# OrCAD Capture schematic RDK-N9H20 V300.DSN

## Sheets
1 PAGE01 - CPU: size B; rev: 1.0; company: for reference; note: N9H20; note: NHS-55FA93 V1.0
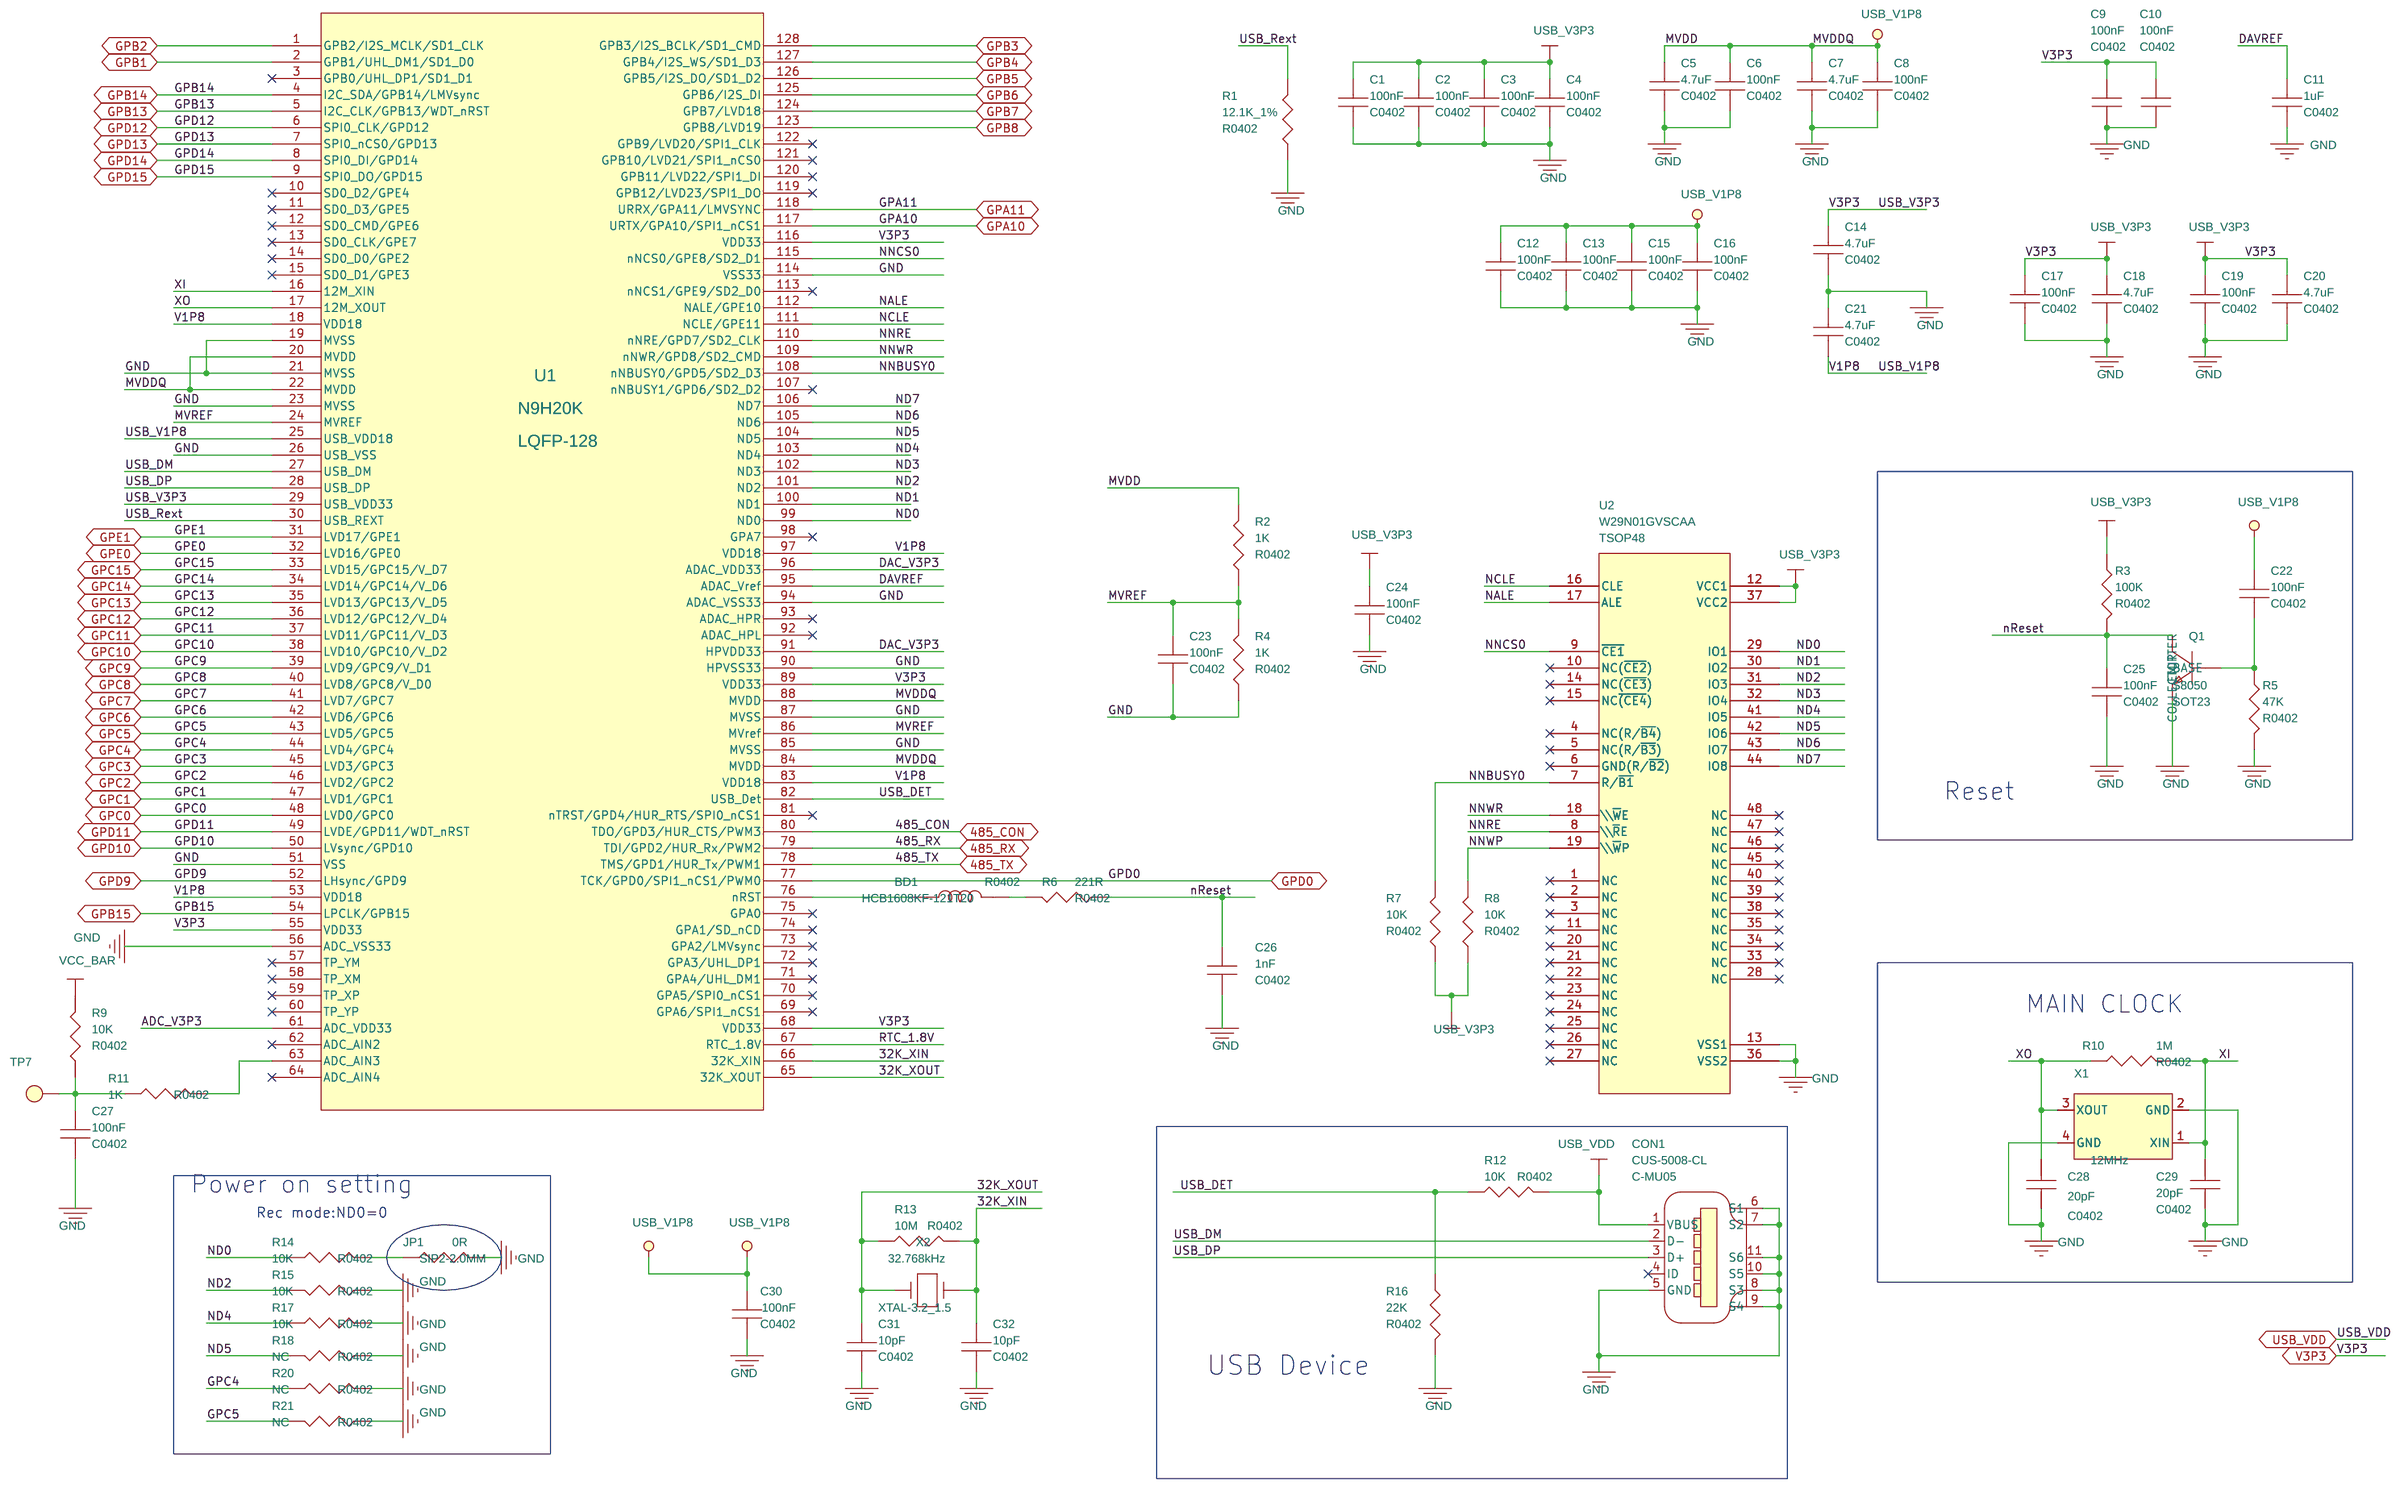
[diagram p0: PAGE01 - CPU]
2 PAGE02 - LCD: size B; note: LCD
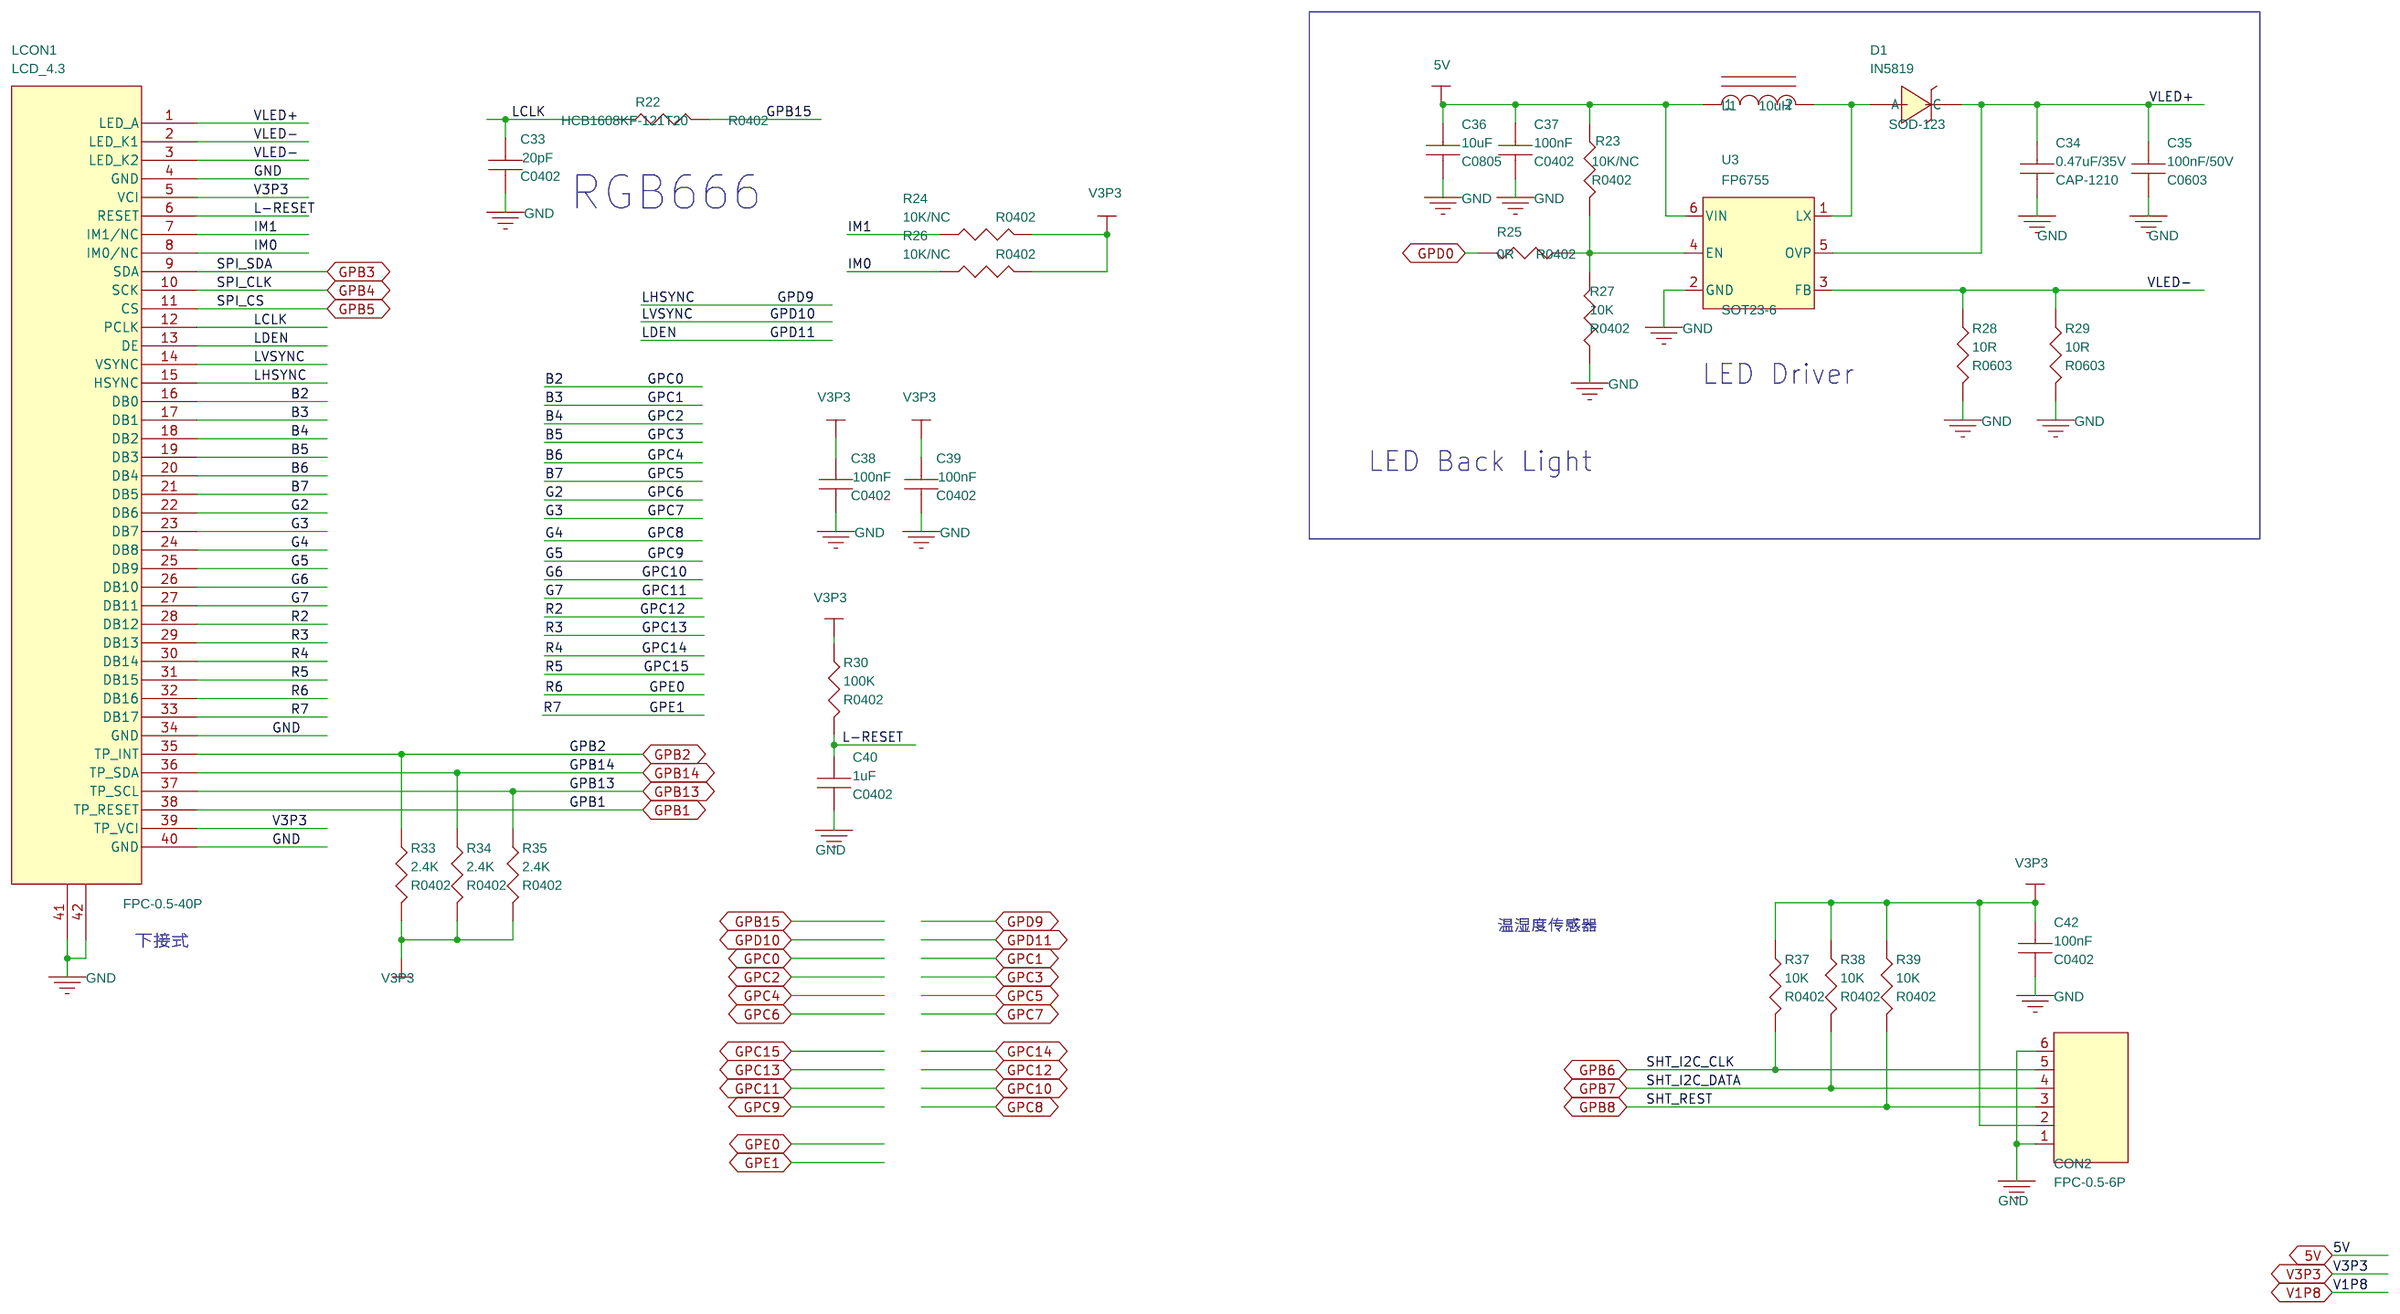
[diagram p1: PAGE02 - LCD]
3 PAGE03 - POWER,Debug: size B; note: POWER,Debug
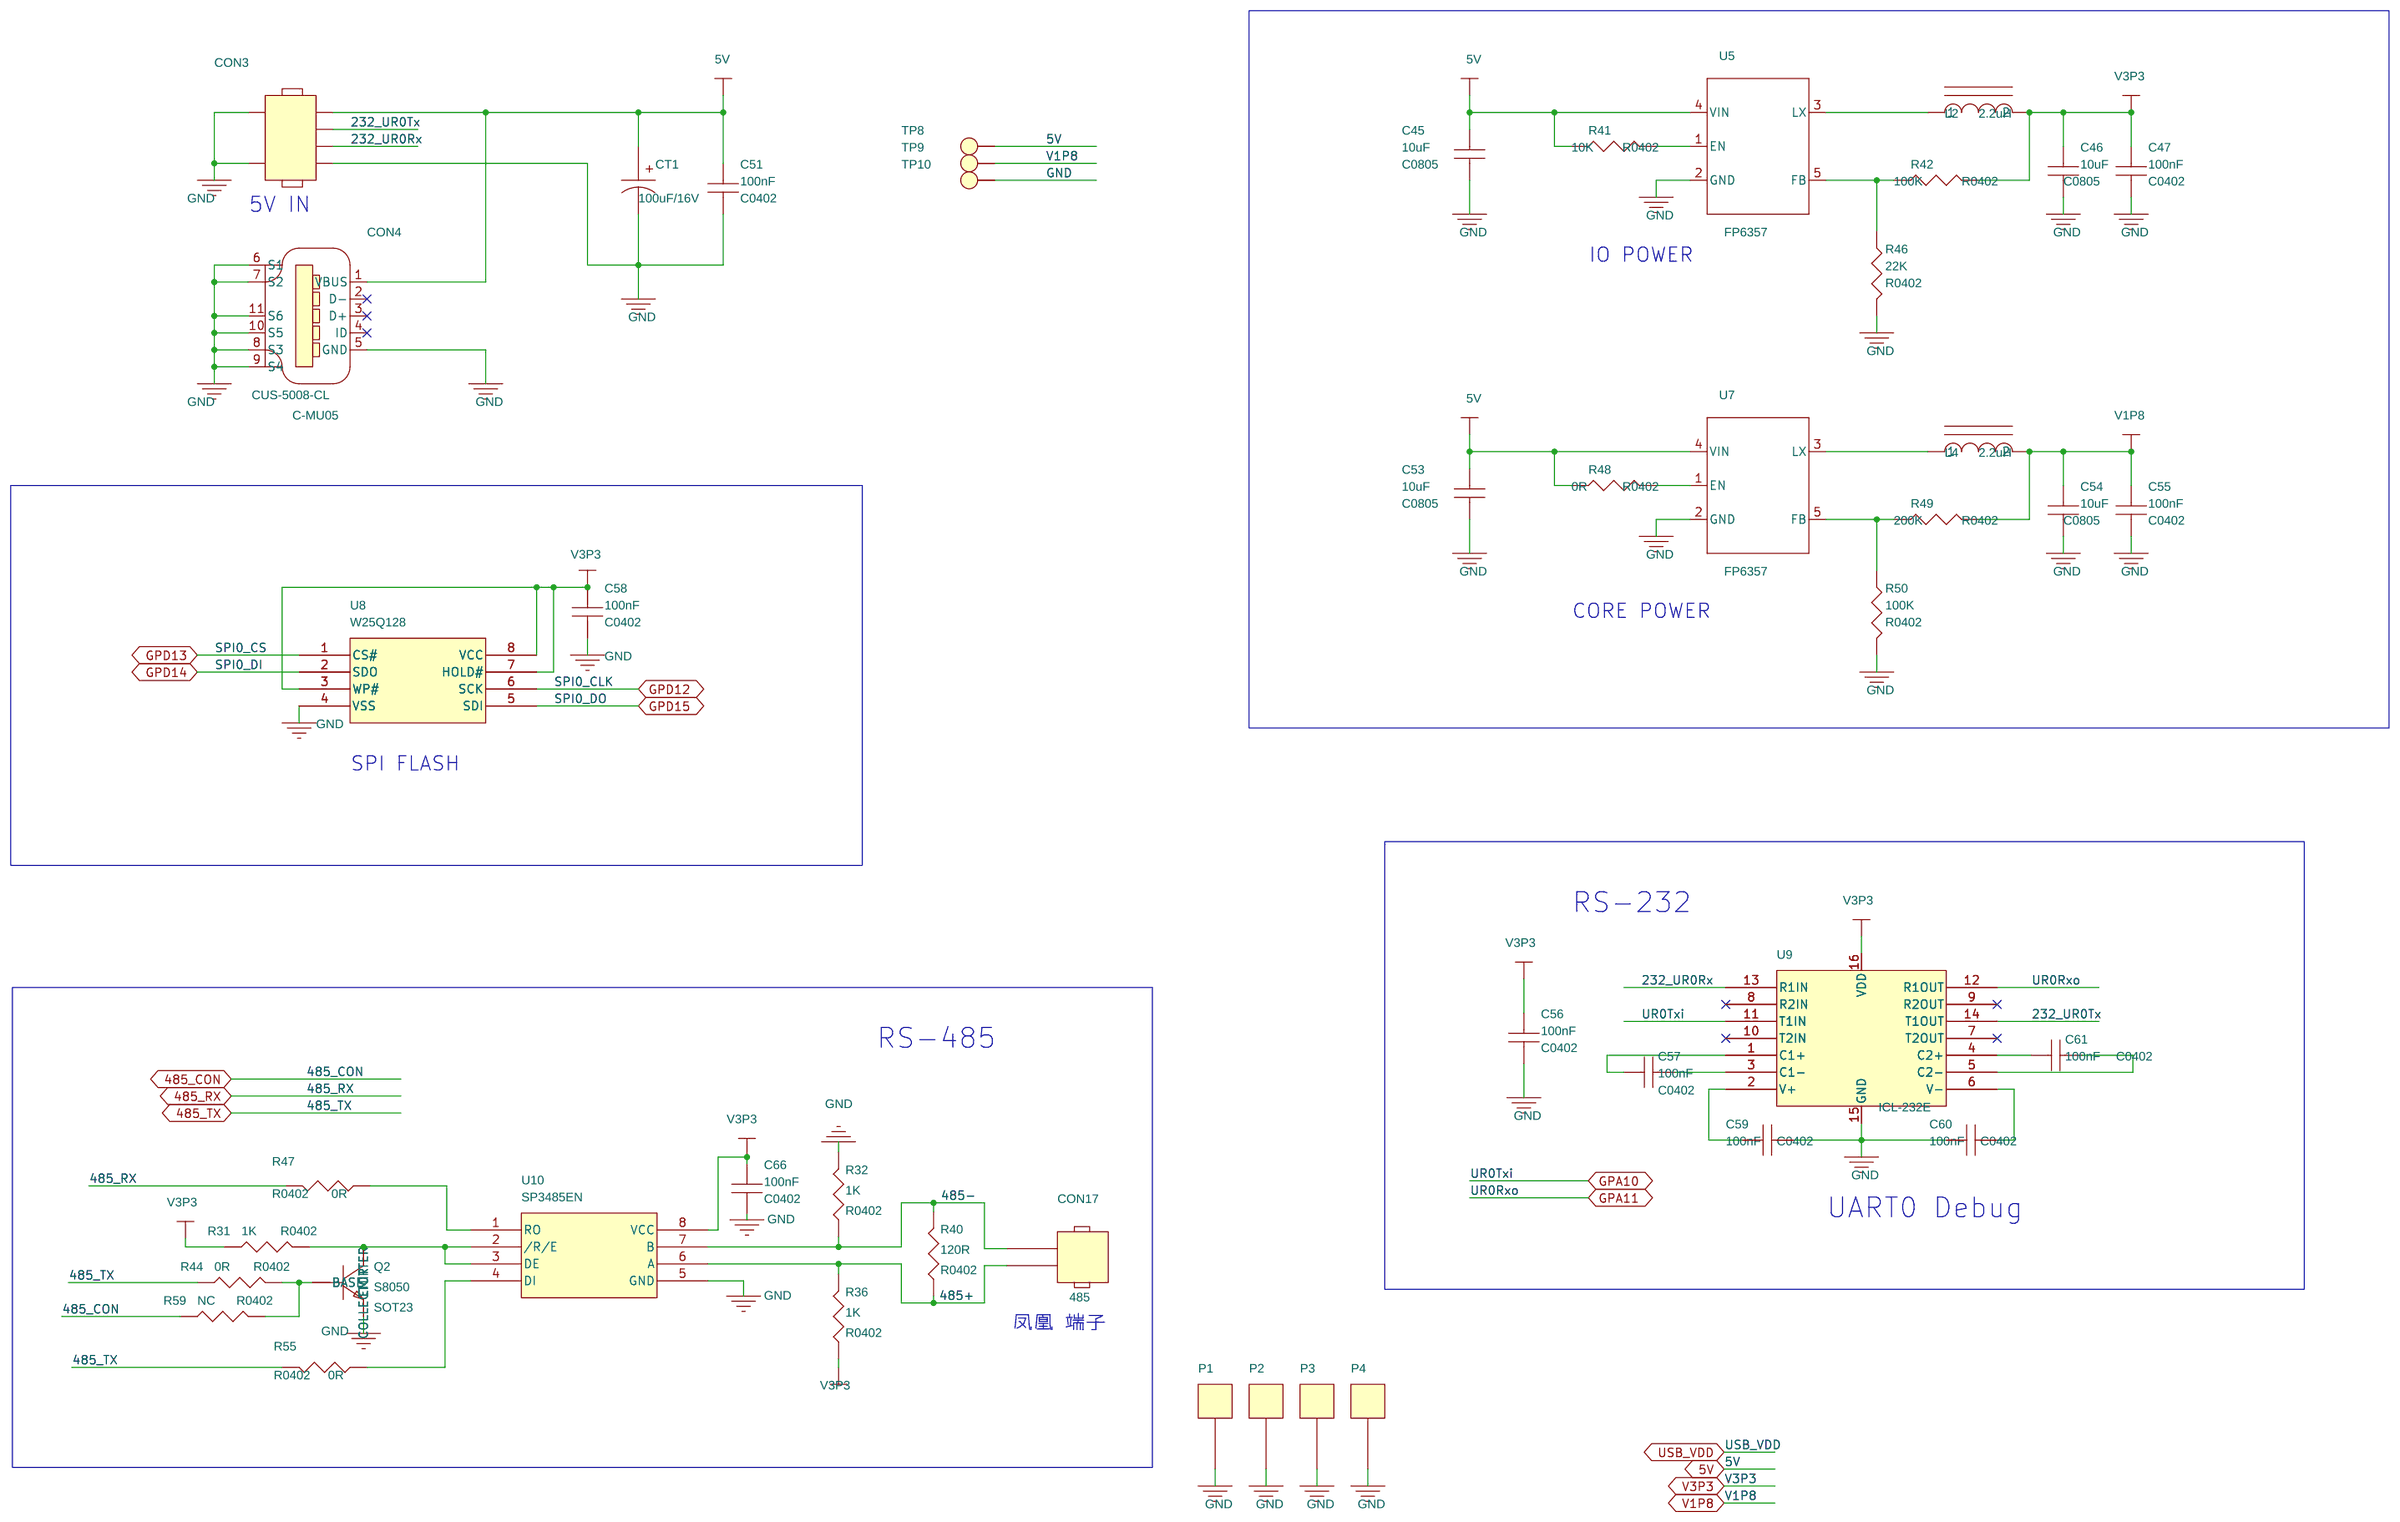
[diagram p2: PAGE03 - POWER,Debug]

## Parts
sheet PAGE01 - CPU
BD1  HCB1608KF-121T20  [R0402]
C1  100nF  [C0402]
C2  100nF  [C0402]
C3  100nF  [C0402]
C4  100nF  [C0402]
C5  4.7uF  [C0402]
C6  100nF  [C0402]
C7  4.7uF  [C0402]
C8  100nF  [C0402]
C9  100nF  [C0402]
C10  100nF  [C0402]
C11  1uF  [C0402]
C12  100nF  [C0402]
C13  100nF  [C0402]
C14  4.7uF  [C0402]
C15  100nF  [C0402]
C16  100nF  [C0402]
C17  100nF  [C0402]
C18  4.7uF  [C0402]
C19  100nF  [C0402]
C20  4.7uF  [C0402]
C21  4.7uF  [C0402]
C22  100nF  [C0402]
C23  100nF  [C0402]
C24  100nF  [C0402]
C25  100nF  [C0402]
C26  1nF  [C0402]
C27  100nF  [C0402]
C28  20pF  [C0402]
C29  20pF  [C0402]
C30  100nF  [C0402]
C31  10pF  [C0402]
C32  10pF  [C0402]
CON1  CUS-5008-CL  [C-MU05]
JP1  0R  [SIP2-2.0MM]
Q1  S8050  [SOT23]
R1  12.1K_1%  [R0402]
R2  1K  [R0402]
R3  100K  [R0402]
R4  1K  [R0402]
R5  47K  [R0402]
R6  221R  [R0402]
R7  10K  [R0402]
R8  10K  [R0402]
R9  10K  [R0402]
R10  1M  [R0402]
R11  1K  [R0402]
R12  10K  [R0402]
R13  10M  [R0402]
R14  10K  [R0402]
R15  10K  [R0402]
R16  22K  [R0402]
R17  10K  [R0402]
R18  NC  [R0402]
R20  NC  [R0402]
R21  NC  [R0402]
TP7  TEST_POINT  [TEST1.1MM]
U1  N9H20K  [LQFP-128]
U2  W29N01GVSCAA  [TSOP48]
X1  12MHz  [CRYSTAL_SMD_1]
X2  32.768kHz  [XTAL-3.2_1.5]
sheet PAGE02 - LCD
C33  20pF  [C0402]
C34  0.47uF/35V  [CAP-1210]
C35  100nF/50V  [C0603]
C36  10uF  [C0805]
C37  100nF  [C0402]
C38  100nF  [C0402]
C39  100nF  [C0402]
C40  1uF  [C0402]
C42  100nF  [C0402]
CON2  FPC-0.5-6P  [FPC-0.5-6P-A]
D1  IN5819  [SOD-123]
L1  10uH  [L-3015]
LCON1  LCD_4.3  [FPC-0.5-40P]
R22  HCB1608KF-121T20  [R0402]
R23  10K/NC  [R0402]
R24  10K/NC  [R0402]
R25  0R  [R0402]
R26  10K/NC  [R0402]
R27  10K  [R0402]
R28  10R  [R0603]
R29  10R  [R0603]
R30  100K  [R0402]
R33  2.4K  [R0402]
R34  2.4K  [R0402]
R35  2.4K  [R0402]
R37  10K  [R0402]
R38  10K  [R0402]
R39  10K  [R0402]
U3  FP6755  [SOT23-6]
sheet PAGE03 - POWER,Debug
C45  10uF  [C0805]
C46  10uF  [C0805]
C47  100nF  [C0402]
C51  100nF  [C0402]
C53  10uF  [C0805]
C54  10uF  [C0805]
C55  100nF  [C0402]
C56  100nF  [C0402]
C57  100nF  [C0402]
C58  100nF  [C0402]
C59  100nF  [C0402]
C60  100nF  [C0402]
C61  100nF  [C0402]
C66  100nF  [C0402]
CON3  XH2.54-4P-A  [XH2.54-4P]
CON4  CUS-5008-CL  [C-MU05]
CON17  485  [DZ2-5.08-A]
CT1  100uF/16V  [SMD-6.3MMX7.7MM]
L2  2.2uH  [L-3015]
L4  2.2uH  [L-3015]
P1  CH1  [FPAD_2]
P2  CH2  [FPAD_2]
P3  CH3  [FPAD_2]
P4  CH4  [FPAD_2]
Q2  S8050  [SOT23]
R31  1K  [R0402]
R32  1K  [R0402]
R36  1K  [R0402]
R40  120R  [R0402]
R41  10K  [R0402]
R42  100K  [R0402]
R44  0R  [R0402]
R46  22K  [R0402]
R47  0R  [R0402]
R48  0R  [R0402]
R49  200K  [R0402]
R50  100K  [R0402]
R55  0R  [R0402]
R59  NC  [R0402]
TP8  TEST_POINT  [TEST1.1MM]
TP9  TEST_POINT  [TEST1.1MM]
TP10  TEST_POINT  [TEST1.1MM]
U5  FP6357  [SOT23-5]
U7  FP6357  [SOT23-5]
U8  W25Q128  [SOIC-8-208SSA]
U9  ICL-232E  [SOP16-150]
U10  SP3485EN  [SOIC-8-208SSA]

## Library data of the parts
BD1 = BLM18PG121SN1
C1-C8 C11-C25 C27 C46 C47 C51 C54 C55 = CAP_0603
C9 C10 C26 C28-C34 C36-C40 C42 C56 C57 C59-C61 C66 = CAP_0402
CON1 CON4 = MiniUSB-B5_1
JP1 R1-R18 R20-R27 R30-R42 R44 R46-R50 R55 R59 = RES_0402
Q1 Q2 = MMBT3904
TP7-TP10 = TEST_POINT
U1 = W55FA93_LCM18_8
U2 = K9LBG08U0D_0
X1 = Crystal_SMD_0
X2 = XTAL_1
C35 C45 C53 C58 = CAP_0805
CON2 = USB-180_1
D1 = ZMM5232B
L1 L2 = INDUCTOR_IRON
LCON1 = LCD_EK08009_7
R28 R29 = RES_0805
U3 = AT1316A
CON3 = HEADER_10_17
CON17 = HEADER_2
CT1 = TAN_A
L4 = INDUCTOR_IRON_1
P1-P4 = CON1
U5 U7 = FP6381AS5_1
U8 = SPI_FLASH-8P_0
U9 = ICL-232E_0
U10 = SPI_FLASH-8P_3

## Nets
5V: C36.1 C37.1 C45.1 C51.1 C53.1 CON3.1 CON4.1(VBUS) CT1.1 L1.1 R23.1 R41.1 R48.1 TP8.1(TP) U3.6(VIN) U5.4(VIN) U7.4(VIN)
GND: C1.2 C2.2 C3.2 C4.2 C5.2 C6.2 C7.2 C8.2 C9.2 C10.2 C11.2 C12.2 C13.2 C14.2 C15.2 C16.2 C17.2 C18.2 C19.2 C20.2 C21.1 C23.2 C24.2 C25.2 C26.2 C27.2 C28.1 C29.1 C30.2 C31.2 C32.2 C33.2 C34.2 C35.2 C36.2 C37.2 C38.2 C39.2 C40.2 C42.2 C45.2 C46.2 C47.2 C51.2 C53.2 C54.2 C55.2 C56.2 C58.2 C59.2 C60.1 C66.2 CON1.5(GND) CON1.6(S1) CON1.7(S2) CON1.8(S3) CON1.9(S4) CON1.10(S5) CON1.11(S6) CON2.1 CON2.6 CON3.4 CON3.5 CON3.6 CON4.5(GND) CON4.6(S1) CON4.7(S2) CON4.8(S3) CON4.9(S4) CON4.10(S5) CON4.11(S6) CT1.2 JP1.2 LCON1.4(GND) LCON1.34(GND) LCON1.40(GND) LCON1.41 LCON1.42 P1.1 P2.1 P3.1 P4.1 Q1.2(EMITTER) Q2.2(EMITTER) R1.1 R4.1 R5.2 R15.1 R16.2 R17.2 R18.1 R20.2 R21.1 R27.1 R28.2 R29.2 R32.2 R46.2 R50.2 TP10.1(TP) U1.19(MVSS) U1.21(MVSS) U1.23(MVSS) U1.26(USB_VSS) U1.51(VSS) U1.56(ADC_VSS33) U1.85(MVSS) U1.87(MVSS) U1.90(HPVSS33) U1.94(ADAC_VSS33) U1.114(VSS33) U2.13(VSS1) U2.36(VSS2) U3.2(GND) U5.2(GND) U7.2(GND) U8.4(VSS) U9.15(GND) U10.5(GND) X1.2(GND) X1.4(GND)
32K_XIN: C32.1 R13.2 U1.66(32K_XIN) X2.1
32K_XOUT: C31.1 R13.1 U1.65(32K_XOUT) X2.2
232_UR0Rx: CON3.3 U9.13(R1IN)
232_UR0Tx: CON3.2 U9.14(T1OUT)
485+: CON17.2 R36.2 R40.1 U10.6(A)
485-: CON17.1 R32.1 R40.2 U10.7(B)
485_CON: R59.1 U1.80(TDO/GPD3/HUR_CTS/PWM3)
485_RX: R47.2 U1.79(TDI/GPD2/HUR_Rx/PWM2)
485_TX: R44.1 R55.2 U1.78(TMS/GPD1/HUR_Tx/PWM1)
ADC_V3P3: C1.1 C2.1 C3.1 C4.1 C9.1 C10.1 C14.1 C17.1 C18.1 C19.1 C20.1 C24.1 C38.1 C39.1 C42.1 C46.1 C47.1 C56.1 C58.1 C66.1 CON2.2 L2.2 LCON1.5(VCI) LCON1.39(TP_VCI) R3.1 R7.1 R8.1 R9.2 R24.2 R26.2 R30.1 R31.1 R33.2 R34.2 R35.2 R36.1 R37.1 R38.1 R39.1 R42.2 U1.29(USB_VDD33) U1.55(VDD33) U1.61(ADC_VDD33) U1.68(VDD33) U1.89(VDD33) U1.91(HPVDD33) U1.96(ADAC_VDD33) U1.116(VDD33) U2.12(VCC1) U2.37(VCC2) U8.3(WP#) U8.7(HOLD#) U8.8(VCC) U9.16(VDD) U10.8(VCC)
DAVREF: C11.1 U1.95(ADAC_Vref)
GPA10: U1.117(URTX/GPA10/SPI1_nCS1) U9.11(T1IN)
GPA11: U1.118(URRX/GPA11/LMVSYNC) U9.12(R1OUT)
GPB1: LCON1.38(TP_RESET) U1.2(GPB1/UHL_DM1/SD1_D0)
GPB2: LCON1.35(TP_INT) R33.1 U1.1(GPB2/I2S_MCLK/SD1_CLK)
GPB3: LCON1.9(SDA) U1.128(GPB3/I2S_BCLK/SD1_CMD)
GPB4: LCON1.10(SCK) U1.127(GPB4/I2S_WS/SD1_D3)
GPB5: LCON1.11(CS) U1.126(GPB5/I2S_DO/SD1_D2)
GPB6: CON2.5 R37.2 U1.125(GPB6/I2S_DI)
GPB7: CON2.4 R38.2 U1.124(GPB7/LVD18)
GPB8: CON2.3 R39.2 U1.123(GPB8/LVD19)
GPB13: LCON1.37(TP_SCL) R35.1 U1.5(I2C_CLK/GPB13/WDT_nRST)
GPB14: LCON1.36(TP_SDA) R34.1 U1.4(I2C_SDA/GPB14/LMVsync)
GPB15: R22.2 U1.54(LPCLK/GPB15)
GPC0: LCON1.16(DB0) U1.48(LVD0/GPC0)
GPC1: LCON1.17(DB1) U1.47(LVD1/GPC1)
GPC2: LCON1.18(DB2) U1.46(LVD2/GPC2)
GPC3: LCON1.19(DB3) U1.45(LVD3/GPC3)
GPC4: LCON1.20(DB4) R20.1 U1.44(LVD4/GPC4)
GPC5: LCON1.21(DB5) R21.2 U1.43(LVD5/GPC5)
GPC6: LCON1.22(DB6) U1.42(LVD6/GPC6)
GPC7: LCON1.23(DB7) U1.41(LVD7/GPC7)
GPC8: LCON1.24(DB8) U1.40(LVD8/GPC8/V_D0)
GPC9: LCON1.25(DB9) U1.39(LVD9/GPC9/V_D1)
GPC10: LCON1.26(DB10) U1.38(LVD10/GPC10/V_D2)
GPC11: LCON1.27(DB11) U1.37(LVD11/GPC11/V_D3)
GPC12: LCON1.28(DB12) U1.36(LVD12/GPC12/V_D4)
GPC13: LCON1.29(DB13) U1.35(LVD13/GPC13/V_D5)
GPC14: LCON1.30(DB14) U1.34(LVD14/GPC14/V_D6)
GPC15: LCON1.31(DB15) U1.33(LVD15/GPC15/V_D7)
GPD0: R25.2 U1.77(TCK/GPD0/SPI1_nCS1/PWM0)
GPD9: LCON1.15(HSYNC) U1.52(LHsync/GPD9)
GPD10: LCON1.14(VSYNC) U1.50(LVsync/GPD10)
GPD11: LCON1.13(DE) U1.49(LVDE/GPD11/WDT_nRST)
GPD12: U1.6(SPI0_CLK/GPD12) U8.6(SCK)
GPD13: U1.7(SPI0_nCS0/GPD13) U8.1(CS#)
GPD14: U1.8(SPI0_DI/GPD14) U8.2(SDO)
GPD15: U1.9(SPI0_DO/GPD15) U8.5(SDI)
GPE0: LCON1.32(DB16) U1.32(LVD16/GPE0)
GPE1: LCON1.33(DB17) U1.31(LVD17/GPE1)
IM0: LCON1.8(IM0/NC) R26.1
IM1: LCON1.7(IM1/NC) R24.1
L-RESET: C40.1 LCON1.6(RESET) R30.2
LCLK: C33.1 LCON1.12(PCLK) R22.1
MVREF: C23.1 R2.1 R4.2 U1.24(MVREF) U1.86(MVref)
NALE: U1.112(NALE/GPE10) U2.17(ALE)
NCLE: U1.111(NCLE/GPE11) U2.16(CLE)
ND0: R14.1 U1.99(ND0) U2.29(IO1)
ND1: U1.100(ND1) U2.30(IO2)
ND2: R15.2 U1.101(ND2) U2.31(IO3)
ND3: U1.102(ND3) U2.32(IO4)
ND4: R17.1 U1.103(ND4) U2.41(IO5)
ND5: R18.2 U1.104(ND5) U2.42(IO6)
ND6: U1.105(ND6) U2.43(IO7)
ND7: U1.106(ND7) U2.44(IO8)
NNBUSY0: R7.2 U1.108(nNBUSY0/GPD5/SD2_D3) U2.7(R/~{B1})
NNCS0: U1.115(nNCS0/GPE8/SD2_D1) U2.9(~{CE1})
NNRE: U1.110(nNRE/GPD7/SD2_CLK) U2.8(\\~{R}E)
NNWP: R8.2 U2.19(\\~{W}P)
NNWR: U1.109(nNWR/GPD8/SD2_CMD) U2.18(\\~{W}E)
nReset: C25.1 C26.1 Q1.3(COLLECTOR) R3.2 R6.1
RTC_1.8V: C5.1 C6.1 C7.1 C8.1 C12.1 C13.1 C15.1 C16.1 C21.2 C22.1 C30.1 C54.1 C55.1 L4.2 R2.2 R49.2 TP9.1(TP) U1.18(VDD18) U1.20(MVDD) U1.22(MVDD) U1.25(USB_VDD18) U1.53(VDD18) U1.67(RTC_1.8V) U1.83(VDD18) U1.84(MVDD) U1.88(MVDD) U1.97(VDD18)
USB_DET: R12.1 R16.1 U1.82(USB_Det)
USB_DM: CON1.2(D-) U1.27(USB_DM)
USB_DP: CON1.3(D+) U1.28(USB_DP)
USB_Rext: R1.2 U1.30(USB_REXT)
USB_VDD: CON1.1(VBUS) R12.2
VLED+: C34.1 C35.1 D1.2(C) LCON1.1(LED_A) U3.5(OVP)
VLED-: LCON1.2(LED_K1) LCON1.3(LED_K2) R28.1 R29.1 U3.3(FB)
XI: C29.2 R10.2 U1.16(12M_XIN) X1.1(XIN)
XO: C28.2 R10.1 U1.17(12M_XOUT) X1.3(XOUT)
N23680262: BD1.2 U1.76(nRST)
N23828437: C22.2 Q1.1(BASE) R5.1
N24004456: BD1.1 R6.2
N24096356: JP1.1 R14.2
N24129764: L2.1 U5.3(LX)
N24129780: R42.1 R46.1 U5.5(FB)
N24129825: R41.2 U5.1(EN)
N24129836: L4.1 U7.3(LX)
N24129840: R49.1 R50.1 U7.5(FB)
N24129897: R48.2 U7.1(EN)
N24131788: R23.2 R25.1 R27.2 U3.4(EN)
N24132027: D1.1(A) L1.2 U3.1(LX)
N24163099: C27.1 R9.1 R11.1 TP7.1(TP)
N24163681: R11.2 U1.63(ADC_AIN3)
N24190323: R55.1 U10.4(DI)
N24190369: Q2.3(COLLECTOR) R31.2 U10.2(/R/E) U10.3(DE)
N24190396: R47.1 U10.1(RO)
N24190503: Q2.1(BASE) R44.2 R59.2
N24192454: C59.1 U9.2(V+)
N24192464: C57.1 U9.1(C1+)
N24192479: C57.2 U9.3(C1-)
N24192556: C60.2 U9.6(V-)
N24192583: C61.1 U9.4(C2+)
N24192585: C61.2 U9.5(C2-)

Not connected (* = marked no-connect by the designer): CON1 4(ID)*; CON4 2(D-)* 3(D+)* 4(ID)*; U1 3(GPB0/UHL_DP1/SD1_D1)* 10(SD0_D2/GPE4)* 11(SD0_D3/GPE5)* 12(SD0_CMD/GPE6)* 13(SD0_CLK/GPE7)* 14(SD0_D0/GPE2)* 15(SD0_D1/GPE3)* 57(TP_YM)* 58(TP_XM)* 59(TP_XP)* 60(TP_YP)* 62(ADC_AIN2)* 64(ADC_AIN4)* 69(GPA6/SPI1_nCS1)* 70(GPA5/SPI0_nCS1)* 71(GPA4/UHL_DM1)* 72(GPA3/UHL_DP1)* 73(GPA2/LMVsync)* 74(GPA1/SD_nCD)* 75(GPA0)* 81(nTRST/GPD4/HUR_RTS/SPI0_nCS1)* 92(ADAC_HPL)* 93(ADAC_HPR)* 98(GPA7)* 107(nNBUSY1/GPD6/SD2_D2)* 113(nNCS1/GPE9/SD2_D0)* 119(GPB12/LVD23/SPI1_DO)* 120(GPB11/LVD22/SPI1_DI)* 121(GPB10/LVD21/SPI1_nCS0)* 122(GPB9/LVD20/SPI1_CLK)*; U2 1(NC)* 2(NC)* 3(NC)* 4(NC(R/~{B4}))* 5(NC(R/~{B3}))* 6(GND(R/~{B2}))* 10(NC(~{CE2}))* 11(NC)* 14(NC(~{CE3}))* 15(NC~{(CE4}))* 20(NC)* 21(NC)* 22(NC)* 23(NC)* 24(NC)* 25(NC)* 26(NC)* 27(NC)* 28(NC)* 33(NC)* 34(NC)* 35(NC)* 38(NC)* 39(NC)* 40(NC)* 45(NC)* 46(NC)* 47(NC)* 48(NC)*; U9 7(T2OUT)* 8(R2IN)* 9(R2OUT)* 10(T2IN)*

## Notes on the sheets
sheet 1
- Reset
- MAIN CLOCK
- Power on setting
- Rec mode:ND0=0
- USB Device
sheet 2
- RGB666
- LED Driver
- LED Back Light
- 温湿度传感器
- 下接式
sheet 3
- 5V IN
- IO POWER
- CORE POWER
- SPI FLASH
- RS-232
- RS-485
- UART0 Debug
- 凤凰 端子
